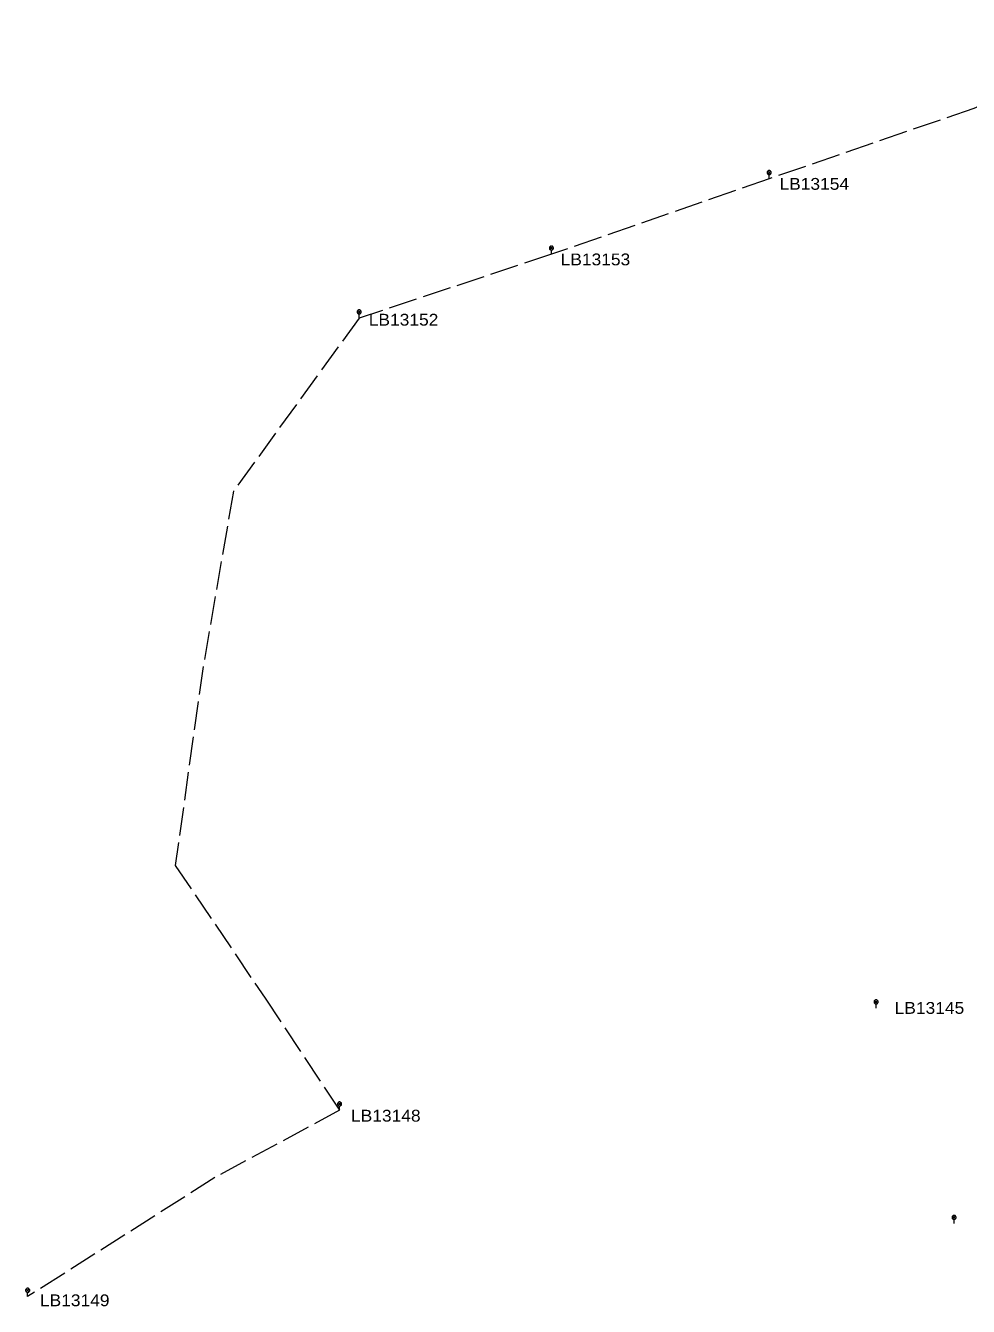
# Model space of a CAD drawing. Extents: x -691843 to -691118, y -976392 to -975793.
# Drawn here: x -691651.8 to -691478.9, y -976192 to -975957.1 of the extents above; entities that cross this region are included whole.
import ezdxf

# ---------------------------------------------------------------- set-up
doc = ezdxf.new("R2010")
doc.units = 0
doc.header["$LTSCALE"] = 0.87
doc.linetypes.add('LONG_DASHED', pattern=[7.5, 6, -1.5])
doc.layers.add('1', color=7, linetype='Continuous', lineweight=13)

msp = doc.modelspace()

# ---------------------------------------------------------------- linework, layer by layer
at = {"layer": '1'}
for p, q in [((-691515.675, -975983.825), (-691515.145, -975984.355)), ((-691515.675, -975984.355), (-691515.145, -975983.825)), ((-691515.41, -975985.24), (-691515.41, -975984.465)), ((-691555.615, -975997.665), (-691555.085, -975998.195)), ((-691555.615, -975998.195), (-691555.085, -975997.665)), ((-691555.35, -975999.08), (-691555.35, -975998.305)), ((-691590.875, -976009.375), (-691590.345, -976009.905)), ((-691590.875, -976009.905), (-691590.345, -976009.375)), ((-691590.61, -976010.79), (-691590.61, -976010.015)), ((-691496.064, -976135.911), (-691495.534, -976136.441)), ((-691496.064, -976136.441), (-691495.534, -976135.911)), ((-691495.799, -976137.326), (-691495.799, -976136.551)), ((-691594.455, -976154.635), (-691593.925, -976155.165)), ((-691594.455, -976155.165), (-691593.925, -976154.635)), ((-691594.19, -976156.05), (-691594.19, -976155.275)), ((-691481.763, -976175.427), (-691481.233, -976175.957)), ((-691481.763, -976175.957), (-691481.233, -976175.427)), ((-691481.498, -976176.842), (-691481.498, -976176.067)), ((-691651.665, -976188.805), (-691651.135, -976189.335)), ((-691651.665, -976189.335), (-691651.135, -976188.805)), ((-691651.4, -976190.22), (-691651.4, -976189.445))]:
    msp.add_line(p, q, dxfattribs=at)
at = {"layer": '1', "linetype": 'LONG_DASHED'}
for points in [[(-691443.2, -975957.14), (-691477.89, -975972.34), (-691515.41, -975985.24), (-691555.35, -975999.08), (-691590.61, -976010.79)], [(-691590.61, -976010.79), (-691613.67, -976042.53), (-691619.21, -976074.65), (-691624.34, -976111.14), (-691607.86, -976135.49), (-691594.19, -976156.05), (-691617.08, -976168.4), (-691651.4, -976190.22)]]:
    msp.add_lwpolyline(points, dxfattribs=at)
at = {"layer": '1'}
for points in [[(-691515.035, -975984.09), (-691515.041, -975984.025), (-691515.058, -975983.962), (-691515.085, -975983.903), (-691515.123, -975983.849), (-691515.169, -975983.803), (-691515.222, -975983.765), (-691515.282, -975983.738), (-691515.345, -975983.721), (-691515.41, -975983.715), (-691515.475, -975983.721), (-691515.538, -975983.738), (-691515.598, -975983.765), (-691515.651, -975983.803), (-691515.697, -975983.849), (-691515.735, -975983.903), (-691515.762, -975983.962), (-691515.779, -975984.025), (-691515.785, -975984.09), (-691515.779, -975984.155), (-691515.762, -975984.218), (-691515.735, -975984.278), (-691515.697, -975984.331), (-691515.651, -975984.377), (-691515.598, -975984.415), (-691515.538, -975984.442), (-691515.475, -975984.459), (-691515.41, -975984.465), (-691515.345, -975984.459), (-691515.282, -975984.442), (-691515.222, -975984.415), (-691515.169, -975984.377), (-691515.123, -975984.331), (-691515.085, -975984.278), (-691515.058, -975984.218), (-691515.041, -975984.155)], [(-691554.975, -975997.93), (-691554.981, -975997.865), (-691554.998, -975997.802), (-691555.025, -975997.742), (-691555.063, -975997.689), (-691555.109, -975997.643), (-691555.162, -975997.605), (-691555.222, -975997.578), (-691555.285, -975997.561), (-691555.35, -975997.555), (-691555.415, -975997.561), (-691555.478, -975997.578), (-691555.538, -975997.605), (-691555.591, -975997.643), (-691555.637, -975997.689), (-691555.675, -975997.742), (-691555.702, -975997.802), (-691555.719, -975997.865), (-691555.725, -975997.93), (-691555.719, -975997.995), (-691555.702, -975998.058), (-691555.675, -975998.117), (-691555.637, -975998.171), (-691555.591, -975998.217), (-691555.538, -975998.255), (-691555.478, -975998.282), (-691555.415, -975998.299), (-691555.35, -975998.305), (-691555.285, -975998.299), (-691555.222, -975998.282), (-691555.162, -975998.255), (-691555.109, -975998.217), (-691555.063, -975998.171), (-691555.025, -975998.117), (-691554.998, -975998.058), (-691554.981, -975997.995)], [(-691590.235, -976009.64), (-691590.241, -976009.575), (-691590.258, -976009.512), (-691590.285, -976009.452), (-691590.323, -976009.399), (-691590.369, -976009.353), (-691590.422, -976009.315), (-691590.482, -976009.288), (-691590.545, -976009.271), (-691590.61, -976009.265), (-691590.675, -976009.271), (-691590.738, -976009.288), (-691590.798, -976009.315), (-691590.851, -976009.353), (-691590.897, -976009.399), (-691590.935, -976009.452), (-691590.962, -976009.512), (-691590.979, -976009.575), (-691590.985, -976009.64), (-691590.979, -976009.705), (-691590.962, -976009.768), (-691590.935, -976009.828), (-691590.897, -976009.881), (-691590.851, -976009.927), (-691590.798, -976009.965), (-691590.738, -976009.992), (-691590.675, -976010.009), (-691590.61, -976010.015), (-691590.545, -976010.009), (-691590.482, -976009.992), (-691590.422, -976009.965), (-691590.369, -976009.927), (-691590.323, -976009.881), (-691590.285, -976009.828), (-691590.258, -976009.768), (-691590.241, -976009.705)], [(-691495.424, -976136.176), (-691495.43, -976136.111), (-691495.447, -976136.048), (-691495.474, -976135.988), (-691495.512, -976135.935), (-691495.558, -976135.889), (-691495.612, -976135.851), (-691495.671, -976135.824), (-691495.734, -976135.807), (-691495.799, -976135.801), (-691495.864, -976135.807), (-691495.927, -976135.824), (-691495.986, -976135.851), (-691496.04, -976135.889), (-691496.086, -976135.935), (-691496.124, -976135.988), (-691496.151, -976136.048), (-691496.168, -976136.111), (-691496.174, -976136.176), (-691496.168, -976136.241), (-691496.151, -976136.304), (-691496.124, -976136.363), (-691496.086, -976136.417), (-691496.04, -976136.463), (-691495.986, -976136.501), (-691495.927, -976136.528), (-691495.864, -976136.545), (-691495.799, -976136.551), (-691495.734, -976136.545), (-691495.671, -976136.528), (-691495.612, -976136.501), (-691495.558, -976136.463), (-691495.512, -976136.417), (-691495.474, -976136.363), (-691495.447, -976136.304), (-691495.43, -976136.241)], [(-691593.815, -976154.9), (-691593.821, -976154.835), (-691593.838, -976154.772), (-691593.865, -976154.712), (-691593.903, -976154.659), (-691593.949, -976154.613), (-691594.003, -976154.575), (-691594.062, -976154.548), (-691594.125, -976154.531), (-691594.19, -976154.525), (-691594.255, -976154.531), (-691594.318, -976154.548), (-691594.378, -976154.575), (-691594.431, -976154.613), (-691594.477, -976154.659), (-691594.515, -976154.712), (-691594.542, -976154.772), (-691594.559, -976154.835), (-691594.565, -976154.9), (-691594.559, -976154.965), (-691594.542, -976155.028), (-691594.515, -976155.088), (-691594.477, -976155.141), (-691594.431, -976155.187), (-691594.378, -976155.225), (-691594.318, -976155.252), (-691594.255, -976155.269), (-691594.19, -976155.275), (-691594.125, -976155.269), (-691594.062, -976155.252), (-691594.003, -976155.225), (-691593.949, -976155.187), (-691593.903, -976155.141), (-691593.865, -976155.088), (-691593.838, -976155.028), (-691593.821, -976154.965)], [(-691481.123, -976175.692), (-691481.129, -976175.627), (-691481.146, -976175.564), (-691481.173, -976175.504), (-691481.211, -976175.451), (-691481.257, -976175.405), (-691481.31, -976175.367), (-691481.37, -976175.34), (-691481.433, -976175.323), (-691481.498, -976175.317), (-691481.563, -976175.323), (-691481.626, -976175.34), (-691481.686, -976175.367), (-691481.739, -976175.405), (-691481.785, -976175.451), (-691481.823, -976175.504), (-691481.85, -976175.564), (-691481.867, -976175.627), (-691481.873, -976175.692), (-691481.867, -976175.757), (-691481.85, -976175.82), (-691481.823, -976175.88), (-691481.785, -976175.933), (-691481.739, -976175.979), (-691481.686, -976176.017), (-691481.626, -976176.044), (-691481.563, -976176.061), (-691481.498, -976176.067), (-691481.433, -976176.061), (-691481.37, -976176.044), (-691481.31, -976176.017), (-691481.257, -976175.979), (-691481.211, -976175.933), (-691481.173, -976175.88), (-691481.146, -976175.82), (-691481.129, -976175.757)], [(-691651.025, -976189.07), (-691651.031, -976189.005), (-691651.048, -976188.942), (-691651.075, -976188.883), (-691651.113, -976188.829), (-691651.159, -976188.783), (-691651.212, -976188.745), (-691651.272, -976188.718), (-691651.335, -976188.701), (-691651.4, -976188.695), (-691651.465, -976188.701), (-691651.528, -976188.718), (-691651.588, -976188.745), (-691651.641, -976188.783), (-691651.687, -976188.829), (-691651.725, -976188.883), (-691651.752, -976188.942), (-691651.769, -976189.005), (-691651.775, -976189.07), (-691651.769, -976189.135), (-691651.752, -976189.198), (-691651.725, -976189.258), (-691651.687, -976189.311), (-691651.641, -976189.357), (-691651.588, -976189.395), (-691651.528, -976189.422), (-691651.465, -976189.439), (-691651.4, -976189.445), (-691651.335, -976189.439), (-691651.272, -976189.422), (-691651.212, -976189.395), (-691651.159, -976189.357), (-691651.113, -976189.311), (-691651.075, -976189.258), (-691651.048, -976189.198), (-691651.031, -976189.135)]]:
    msp.add_lwpolyline(points, close=True, dxfattribs=at)

# ---------------------------------------------------------------- texts
at = {"layer": '1', "width": 1.1}
for s, p in [('LB13154', (-691513.514, -975987.245)), ('LB13153', (-691553.65, -976001.099)), ('LB13152', (-691588.841, -976012.157)), ('LB13145', (-691492.392, -976138.364)), ('LB13148', (-691592.093, -976158.127)), ('LB13149', (-691649.15, -976191.982))]:
    msp.add_text(s, height=2.167, dxfattribs=at).set_placement(p)

doc.saveas('drawing.dxf')
